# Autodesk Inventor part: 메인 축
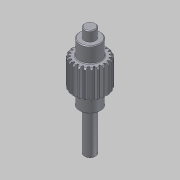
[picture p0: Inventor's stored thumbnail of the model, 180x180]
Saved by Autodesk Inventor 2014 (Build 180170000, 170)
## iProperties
Created: 2014-07
Part Number: 메인 축
Material: 강
Document SubType Name: Modeling
Designer: KYOUNG IL JANG
Categories: <?xml version="1.0" encoding="UTF-16"?> <MemberInstance><Categories><FamilyTemplate><FamilyTemplateParameter ValueType="xs:double" Id="1" ObjectReferenceKey="da
Density: 1 g/cm^3
Appearance: 강철
CustomPartVersion: 1
Company: 한국ATC센터
Author: KYOUNG IL JANG
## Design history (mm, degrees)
sketch "Sketch1"
  geometry: C1 r 12 at (0, 0)
  constraints: 1 centre point
  dimensions: "d0" = 24 diameter of C1 (= da_da)
extrude "Extrusion1" new body sketch "Sketch1" distance "d1" = 20 (= da_b); taper "d2" = 0 deg
workplane "Work Plane2"
feature "피치 지름" dims "d4" = 10, "d5" = 0
workplane "Work Plane8"
workplane "Work Plane9"
chamfer "모따기1" distance "d49" = 1; stored, may be unused: second distance "d50" = 2, angle "d51" = 45 deg
sketch "스케치3"
  geometry: C1 r 7.5 at (0, 0); 1 further point
  constraints: 1 centre point, 1 coincident
  dimensions: "d52" = 15 diameter of C1
extrude "돌출2" join sketch "스케치3" distance "d53" = 11; taper "d54" = 0 deg
sketch "스케치4"
  geometry: C1 r 4 at (0, 0); 1 further point
  constraints: 1 centre point, 1 coincident
  dimensions: "d55" = 8 diameter of C1
extrude "돌출3" join sketch "스케치4" distance "d56" = 7; taper "d57" = 0 deg
sketch "스케치5"
  geometry: C1 r 7.5 at (0, 0) reference; C2 r 7.5 at (0, 0) reference; 1 further point
extrude "돌출4" join sketch "스케치5" distance "d62" = 11; taper "d63" = 0 deg
sketch "스케치6"
  geometry: C1 r 4 at (0, 0); 1 further point
  constraints: 1 centre point, 1 coincident
  dimensions: "d64" = 8 diameter of C1
extrude "돌출5" join sketch "스케치6" distance "d65" = 30; taper "d66" = 0 deg
chamfer "모따기2" distance "d58" = 0.5; stored, may be unused: second distance "d59" = 2, angle "d60" = 45 deg
fillet "모깎기1" dims "d61" = 0.5
feature "스퍼 기어" dims "da_b" = 20, "da_d" = 22, "da_aw" = 31, "da_da" = 24, "da_df" = 19.5, "da_dw" = 22, angle "da_beta" = 0 deg, "da_lefttooth" = 0, "da_righttooth" = 0
body "Solid1"
sketch "Sketch2"
  geometry: C1 r 12 at (0, 0) reference; C2 r 11 at (0, 0)
  constraints: 1 centre point, 1 coincident
  dimensions: "d3" = 22 diameter of C2 (= da_dw)
body "Srf1"
node "투영된 루프1"
other parameters: "d16" = 31 (= da_aw), "d17" = 0, "d34" = 1.428 (computed from da_z), "d39" = 0, "d41" = 0, "d43" = 31 (= da_aw), "d46" = 31 (= da_aw), "d47" = 0, "d48" = 0
